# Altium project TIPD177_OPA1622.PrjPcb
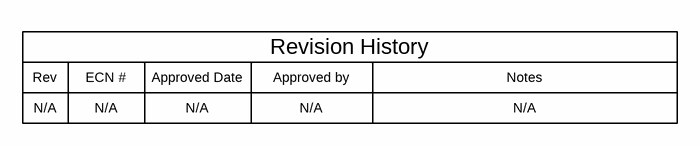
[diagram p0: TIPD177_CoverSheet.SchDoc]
TID: TIPD177; TechSupport: http://www.ti.com/support; SCH_Rev: E1; PRJ_Title: Headphone Amplifier; PRJ_Number: TIPD177; PRJ_Engineer: JC, CW; PRJ_Customer: Public Release; PCB_Rev: E1; PCB_Layout: CW; CopyrightYear: 2016
3 sheets, 71 parts. Net scope: global (net labels, ports and power ports of the same name join across sheets).
Board file: TIPD177.PcbDoc
Sheets:
  TIPD177_CoverSheet.SchDoc
  TIPD177_Main.SchDoc
  TIPD177_Hardware.SchDoc

## Sheet TIPD177_CoverSheet.SchDoc
size 431 x 279 mm; Date: Not shown in title block; ApprovedBy: Not shown in title block; CheckedBy: Not shown in title block; Author: Not shown in title block; CompanyName: Not shown in title block; Engineer: Not shown in title block; Organization: Not shown in title block; Address1: Not shown in title block; Address2: Not shown in title block; Address3: Not shown in title block; Address4: Not shown in title block; DocumentNumber: 1; Revision: Use project parameter SCH_Rev; SheetNumber: 1; SheetTotal: 3; PageSetup: Record=PageOptions¦CenterHorizontal=True¦CenterVertical=True¦PrintScale=1.00¦XCorrection=1.00¦YCorrection=1.00¦PrintKind=0¦BorderSize=5000000¦LeftOffset=0¦BottomOffset=0¦Orientation=2¦PaperLength=1000¦PaperWidth=1000¦Scale=100¦PaperSource=15¦PrintQuality=600¦MediaType=1¦DitherType=10¦PaperKind=Letter¦PrintScaleMode=1

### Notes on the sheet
- Rev
- N/A
- ECN #
- Approved Date
- Approved by
- Revision History
- Notes

## Sheet TIPD177_Main.SchDoc
size 431 x 279 mm; Date: Not shown in title block; ApprovedBy: Not shown in title block; CheckedBy: Not shown in title block; Author: Not shown in title block; CompanyName: Not shown in title block; Engineer: Not shown in title block; Organization: Not shown in title block; Address1: Not shown in title block; Address2: Not shown in title block; Address3: Not shown in title block; Address4: Not shown in title block; DocumentNumber: 1; Revision: Use project parameter SCH_Rev; SheetNumber: 2; SheetTotal: 3; PageSetup: Record=PageOptions¦CenterHorizontal=True¦CenterVertical=True¦PrintScale=0.62¦XCorrection=1.00¦YCorrection=1.00¦PrintKind=0¦BorderSize=5000000¦LeftOffset=0¦BottomOffset=0¦Orientation=2¦PaperLength=1000¦PaperWidth=1000¦Scale=100¦PaperSource=15¦PrintQuality=600¦MediaType=1¦DitherType=10¦PrintScaleMode=1¦PaperKind=Letter
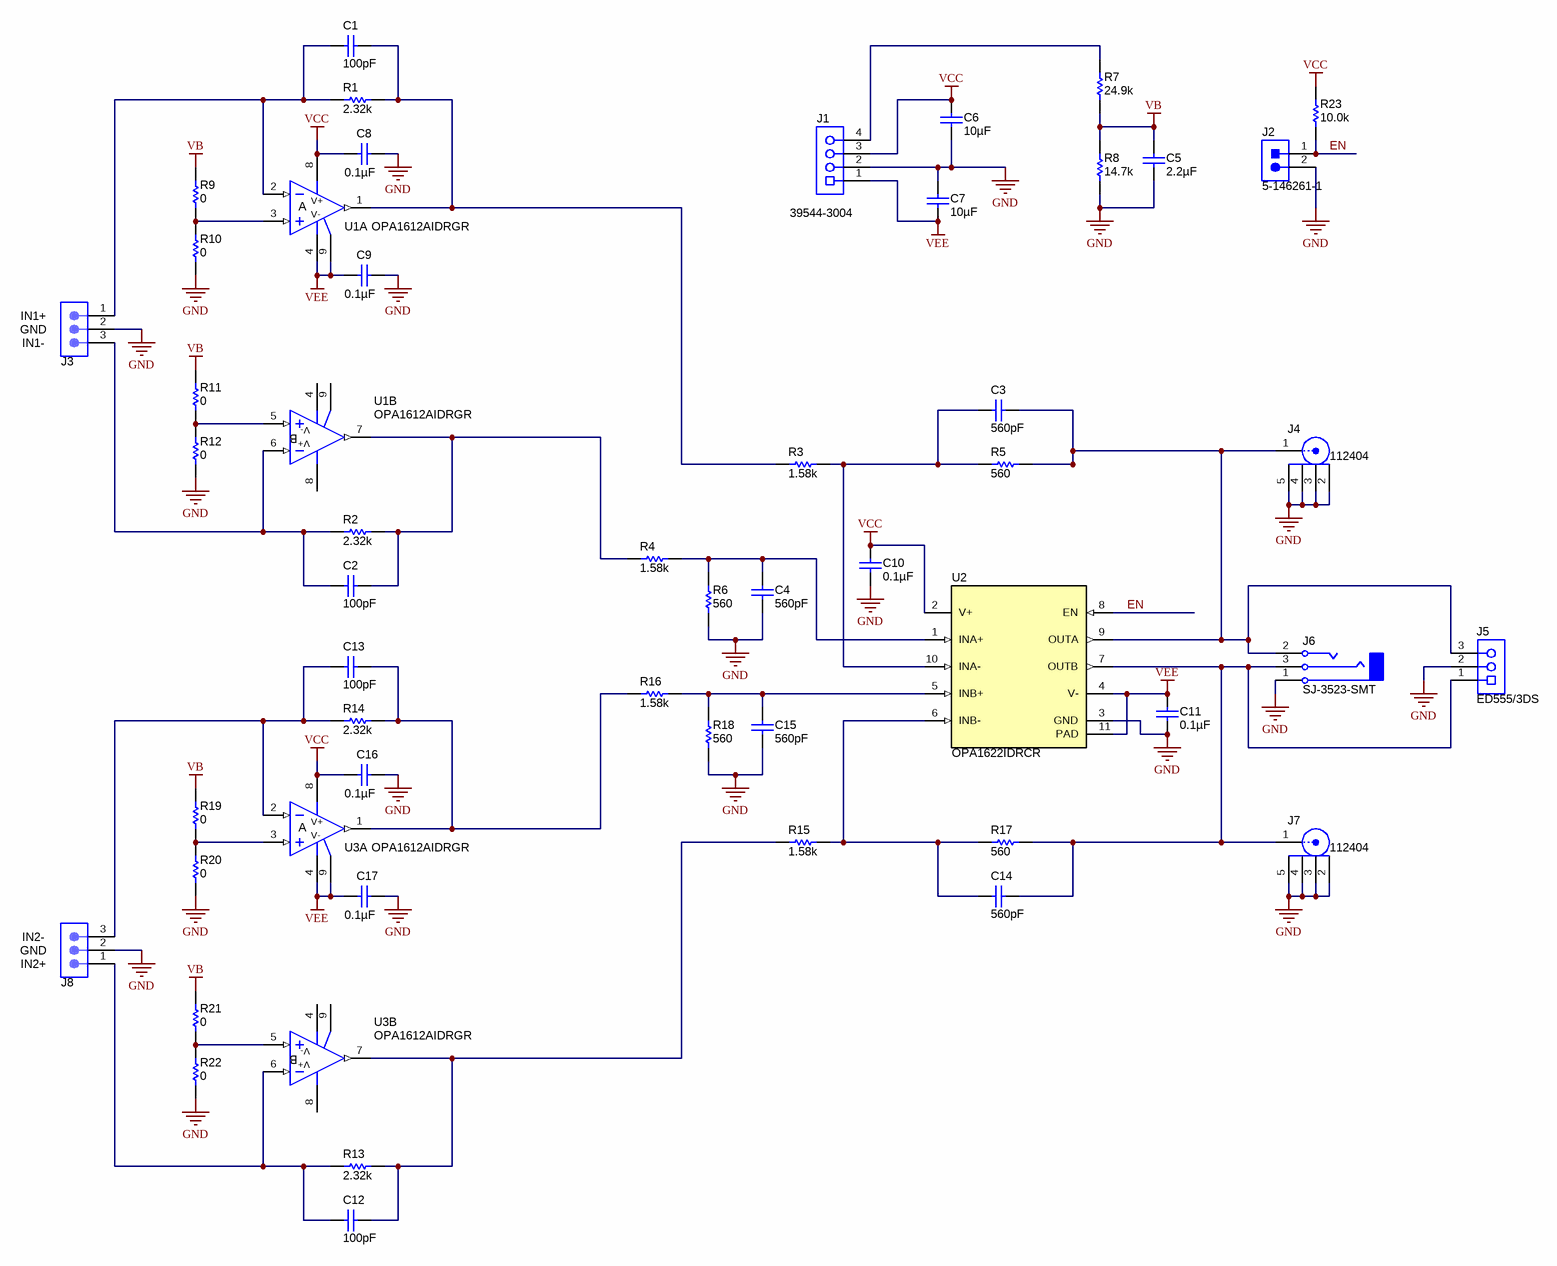
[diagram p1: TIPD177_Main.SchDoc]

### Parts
C1  ValueDisplayed: 100pF  [0603]  (hidden comment: GRM1885C1H101JA01D)
C2  ValueDisplayed: 100pF  [0603]  (hidden comment: GRM1885C1H101JA01D)
C3  ValueDisplayed: 560pF  [0603]  (hidden comment: GRM1885C1H561JA01D)
C4  ValueDisplayed: 560pF  [0603]  (hidden comment: GRM1885C1H561JA01D)
C5  ValueDisplayed: 2.2µF  [1206]  (hidden comment: GRM316R61E225KA12D)
C6  ValueDisplayed: 10µF  [1206]  (hidden comment: C3216X5R1C106M)
C7  ValueDisplayed: 10µF  [1206]  (hidden comment: C3216X5R1C106M)
C8  ValueDisplayed: 0.1µF  [0603]  (hidden comment: GRM188R71H104KA93D)
C9  ValueDisplayed: 0.1µF  [0603]  (hidden comment: GRM188R71H104KA93D)
C10  ValueDisplayed: 0.1µF  [0603]  (hidden comment: GRM188R71H104KA93D)
C11  ValueDisplayed: 0.1µF  [0603]  (hidden comment: GRM188R71H104KA93D)
C12  ValueDisplayed: 100pF  [0603]  (hidden comment: GRM1885C1H101JA01D)
C13  ValueDisplayed: 100pF  [0603]  (hidden comment: GRM1885C1H101JA01D)
C14  ValueDisplayed: 560pF  [0603]  (hidden comment: GRM1885C1H561JA01D)
C15  ValueDisplayed: 560pF  [0603]  (hidden comment: GRM1885C1H561JA01D)
C16  ValueDisplayed: 0.1µF  [0603]  (hidden comment: GRM188R71H104KA93D)
C17  ValueDisplayed: 0.1µF  [0603]  (hidden comment: GRM188R71H104KA93D)
J1  39544-3004  [MOLEX_39544-3004]
J2  5-146261-1  [CONN_5-146261-1]
J3  PBC03SAAN  [PBC03SAAN]  (value not drawn)
J4  112404  [Amphenol_112404]
J5  ED555/3DS  [TERM_BLK_ED555-3DS]
J6  SJ-3523-SMT  [CUI_SJ-3523-SMT]
J7  112404  [Amphenol_112404]
J8  PBC03SAAN  [PBC03SAAN]  (value not drawn)
R1  ValueDisplayed: 2.32k  [0603]  (hidden comment: RT0603BRD072K32L)
R2  ValueDisplayed: 2.32k  [0603]  (hidden comment: RT0603BRD072K32L)
R3  ValueDisplayed: 1.58k  [0603]  (hidden comment: RT0603BRD071K58L)
R4  ValueDisplayed: 1.58k  [0603]  (hidden comment: RT0603BRD071K58L)
R5  ValueDisplayed: 560  [0603]  (hidden comment: RG1608P-561-B-T5)
R6  ValueDisplayed: 560  [0603]  (hidden comment: RG1608P-561-B-T5)
R7  ValueDisplayed: 24.9k  [0603]  (hidden comment: RT0603BRD0724K9L)
R8  ValueDisplayed: 14.7k  [0603]  (hidden comment: RT0603BRD0714K7L)
R9  ValueDisplayed: 0  [0603]  (hidden comment: CRCW06030000Z0EA)
R10  ValueDisplayed: 0  [0603]  (hidden comment: CRCW06030000Z0EA)
R11  ValueDisplayed: 0  [0603]  (hidden comment: CRCW06030000Z0EA)
R12  ValueDisplayed: 0  [0603]  (hidden comment: CRCW06030000Z0EA)
R13  ValueDisplayed: 2.32k  [0603]  (hidden comment: RT0603BRD072K32L)
R14  ValueDisplayed: 2.32k  [0603]  (hidden comment: RT0603BRD072K32L)
R15  ValueDisplayed: 1.58k  [0603]  (hidden comment: RT0603BRD071K58L)
R16  ValueDisplayed: 1.58k  [0603]  (hidden comment: RT0603BRD071K58L)
R17  ValueDisplayed: 560  [0603]  (hidden comment: RG1608P-561-B-T5)
R18  ValueDisplayed: 560  [0603]  (hidden comment: RG1608P-561-B-T5)
R19  ValueDisplayed: 0  [0603]  (hidden comment: CRCW06030000Z0EA)
R20  ValueDisplayed: 0  [0603]  (hidden comment: CRCW06030000Z0EA)
R21  ValueDisplayed: 0  [0603]  (hidden comment: CRCW06030000Z0EA)
R22  ValueDisplayed: 0  [0603]  (hidden comment: CRCW06030000Z0EA)
R23  value 10.0k  [0603]  (hidden comment: CRCW060310K0FKEA)
U1  OPA1612AIDRGR  [DRG0008A]  (parts A,B of 2)
U2  OPA1622IDRCR  [DRC0010J]
U3  OPA1612AIDRGR  [DRG0008A]  (parts A,B of 2)

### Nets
GND: C4.1 C5.2 C6.2 C7.2 C8.1 C9.1 C10.2 C11.2 C15.1 C16.1 C17.1 J1.2 J2.2 J3.2 J4.2 J4.3 J4.4 J4.5 J5.2 J6.1(SLEEVE) J7.2 J7.3 J7.4 J7.5 J8.2 R6.2 R8.1 R10.1 R12.1 R18.2 R20.1 R22.1 U2.3(GND)
VB: C5.1 R7.1 R8.2 R9.2 R11.2 R19.2 R21.2
VCC: C6.1 C8.2 C10.1 C16.2 J1.3 R23.2 U1.8(V+) U2.2(V+) U3.8(V+)
VEE: C7.1 C9.2 C11.1 C17.2 J1.1 U1.4(V-) U1.9(PAD) U2.4(V-) U2.11(PAD) U3.4(V-) U3.9(PAD)
EN: J2.1 R23.1 U2.8(EN)
NetC1_1: C1.1 R1.2 R3.1 U1.1(OUT)
NetC1_2: C1.2 J3.1 R1.1 U1.2(IN-)
NetC2_1: C2.1 R2.2 R4.1 U1.7(OUT)
NetC2_2: C2.2 J3.3 R2.1 U1.6(IN-)
NetC3_1: C3.1 J4.1 J5.3 J6.2(TIP) R5.2 U2.9(OUTA)
NetC3_2: C3.2 R3.2 R5.1 U2.10(INA-)
NetC4_2: C4.2 R4.2 R6.1 U2.1(INA+)
NetC12_1: C12.1 R13.2 R15.1 U3.7(OUT)
NetC12_2: C12.2 J8.1 R13.1 U3.6(IN-)
NetC13_1: C13.1 R14.2 R16.1 U3.1(OUT)
NetC13_2: C13.2 J8.3 R14.1 U3.2(IN-)
NetC14_1: C14.1 J5.1 J6.3(RING) J7.1 R17.2 U2.7(OUTB)
NetC14_2: C14.2 R15.2 R17.1 U2.6(INB-)
NetC15_2: C15.2 R16.2 R18.1 U2.5(INB+)
NetJ1_4: J1.4 R7.2
NetR9_1: R9.1 R10.2 U1.3(IN+)
NetR11_1: R11.1 R12.2 U1.5(IN+)
NetR19_1: R19.1 R20.2 U3.3(IN+)
NetR21_1: R21.1 R22.2 U3.5(IN+)

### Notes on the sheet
- (near J3) IN1-
- (near J3) IN1+
- (near J3) GND
- (near J8) IN2-
- (near J8) GND
- (near J8) IN2+

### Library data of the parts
C1 C2 C12 C13 = GRM1885C1H101JA01D: CAP, CERM, 100 pF, 50 V, +/- 5%, C0G/NP0, 0603; Manufacturer: MuRata; Polarized: N; CompType: Capacitor; Value: 100pF; U/M: EA; Cap_F: 0.0000000001; Tolerance_%: 5; Value1: Unknown; VDC_V: 50; Value2: 50V; TaMin_C: -55; TaMax_C: 125; AEC Category: Q200
C3 C4 C14 C15 = GRM1885C1H561JA01D: CAP, CERM, 560 pF, 50 V, +/- 5%, C0G/NP0, 0603; Manufacturer: MuRata; Polarized: N; CompType: Capacitor; Value: 560pF; U/M: EA; Cap_F: 0.00000000056; Tolerance_%: 5; Value1: Unknown; VDC_V: 50; Value2: 50V; TaMin_C: -55; TaMax_C: 125; AEC Category: Q200
C5 = GRM316R61E225KA12D: CAP, CERM, 2.2uF, 25V, +/-10%, X5R, 1206; Manufacturer: MuRata; Polarized: N; CompType: Capacitor; U/M: EA; Cap_F: 0.0000022; Tolerance_%: 10; ESR_Ohm: 0.006; Value1: 0.006 ohm; VDC_V: 25; TaMin_C: -55; TaMax_C: 85
C6 C7 = C3216X5R1C106M: CAP, CERM, 10uF, 16V, +/-20%, X5R, 1206; Manufacturer: TDK; Polarized: N; CompType: Capacitor; U/M: EA; Cap_F: 0.00001; Tolerance_%: 20; ESR_Ohm: 0.0046; Value1: 0.0046 ohm; VDC_V: 16; IRMS_A: 2.7; TaMin_C: -55; TaMax_C: 85
C8-C11 C16 C17 = GRM188R71H104KA93D: CAP, CERM, 0.1 µF, 50 V, +/- 10%, X7R, 0603; Manufacturer: MuRata; Polarized: N; CompType: Capacitor; Value: 0.1uF; U/M: EA; Cap_F: 0.0000001; Tolerance_%: 10; Value1: Unknown; VDC_V: 50; Value2: 50V; TaMin_C: -55; TaMax_C: 125; AEC Category: Q200
J1 = 39544-3004: Terminal Block, 4x1, 5.08mm, TH; Manufacturer: Molex; SymbolCreator: a0411947
J2 = 5-146261-1: Header, 100mil, 2x1, Gold, TH; Manufacturer: TE Connectivity; SymbolCreator: a0412235
J3 J8 = PBC03SAAN: Header, 100mil, 3x1, Gold, TH; Manufacturer: Sullins Connector Solutions
J4 J7 = 112404: Connector, TH, BNC; Manufacturer: Amphenol Connex
J5 = ED555/3DS: Terminal Block, 3.5mm Pitch, 3x1, TH; Manufacturer: On-Shore Technology; SymbolCreator: a0412235; Pitch_mm: 3.5; Gender: Female; Shrouded: N; Row_Count: 1; ContactFinish: Brass; Current_A: 6; Voltage_V: 150; Cert_CULUS: Y
J6 = SJ-3523-SMT: Audio Jack, 3.5mm, Stereo, R/A, SMT; Manufacturer: CUI Inc.; SymbolCreator: a0412235
R1 R2 R13 R14 = RT0603BRD072K32L: RES, 2.32 k, 0.1%, 0.1 W, 0603; Manufacturer: Yageo America; CompType: Resistor; Value: 2.32k; Res_ohm: 2320; Value_Code: 2k32; Tolerance_%: 0.1; Value2: 0.1W; VDC_V: 75; TempCo: 25 ppm/C; EIA_Code: E192; U/M: EA; AEC Category: Q200
R3 R4 R15 R16 = RT0603BRD071K58L: RES, 1.58 k, 0.1%, 0.1 W, 0603; Manufacturer: Yageo America; CompType: Resistor; Value: 1.58k; Res_ohm: 1580; Value_Code: 1k58; Tolerance_%: 0.1; Value2: 0.1W; VDC_V: 75; TempCo: 25 ppm/C; EIA_Code: E192; U/M: EA; AEC Category: Q200
R5 R6 R17 R18 = RG1608P-561-B-T5: RES, 560, 0.1%, 0.1 W, 0603; Manufacturer: Susumu Co Ltd; CompType: Resistor; Value: 560; Value_Code: 560R; Tolerance_%: 0.1; Value2: 0.1W; VDC_V: 75; TempCo: 25 ppm/C; U/M: EA; AEC Category: Q200
R7 = RT0603BRD0724K9L: RES, 24.9 k, 0.1%, 0.1 W, 0603; Manufacturer: Yageo America; CompType: Resistor; Value: 24.9k; Res_ohm: 24900; Value_Code: 24k9; Tolerance_%: 0.1; Value2: 0.1W; VDC_V: 75; TempCo: 25 ppm/C; EIA_Code: E192; U/M: EA; AEC Category: Q200
R8 = RT0603BRD0714K7L: RES, 14.7 k, 0.1%, 0.1 W, 0603; Manufacturer: Yageo America; CompType: Resistor; Value: 14.7k; Res_ohm: 14700; Value_Code: 14k7; Tolerance_%: 0.1; Value2: 0.1W; VDC_V: 75; TempCo: 25 ppm/C; EIA_Code: E192; U/M: EA; AEC Category: Q200
R9-R12 R19-R22 = CRCW06030000Z0EA: RES, 0, 5%, 0.1 W, 0603; Manufacturer: Vishay-Dale; CompType: Resistor; Value: 0; Value_Code: 0000; Tolerance_%: 5; Power_W: 0.1; Value2: 0.1W; VDC_V: 75; TempCo: 200 ppm/C; EIA_Code: E24; U/M: EA; AEC Category: Q200
R23 = CRCW060310K0FKEA: RES, 10.0k ohm, 1%, 0.1W, 0603; Manufacturer: Vishay-Dale; CompType: Resistor; Res_ohm: 10000; Value_Code: 10k0; Tolerance_%: 1; Power_W: 0.1; VDC_V: 75; TempCo: 100 ppm/C; EIA_Code: E96; U/M: EA
U1 U3 = OPA1612AIDRGR: SoundPlus High-Performance, Bipolar-Input Audio Operational Amplifiers, DRG0008A; Alternate PartNumber: OPA1612AIDRGT; Manufacturer: Texas Instruments; SymbolCreator: a0411947; CompType: IC; U/M: EA
U2 = OPA1622IDRCR: SoundPlus High-Fidelity, Bipolar-Input, Audio Operational Amplifier, DRC0010J; Alternate PartNumber: OPA1622IDRCT; Manufacturer: Texas Instruments; SymbolCreator: Altium; CompType: IC; U/M: EA

## Sheet TIPD177_Hardware.SchDoc
size 431 x 279 mm; Date: Not shown in title block; ApprovedBy: Not shown in title block; CheckedBy: Not shown in title block; Author: Not shown in title block; CompanyName: Not shown in title block; Engineer: Not shown in title block; Organization: Not shown in title block; Address1: Not shown in title block; Address2: Not shown in title block; Address3: Not shown in title block; Address4: Not shown in title block; DocumentNumber: 1; Revision: Use project parameter SCH_Rev; SheetNumber: 3; SheetTotal: 3; PageSetup: Record=PageOptions¦CenterHorizontal=True¦CenterVertical=True¦PrintScale=1.00¦XCorrection=1.00¦YCorrection=1.00¦PrintKind=0¦BorderSize=5000000¦LeftOffset=0¦BottomOffset=0¦Orientation=2¦PaperLength=1000¦PaperWidth=1000¦Scale=100¦PaperSource=15¦PrintQuality=600¦MediaType=1¦DitherType=10¦PaperKind=Letter¦PrintScaleMode=1
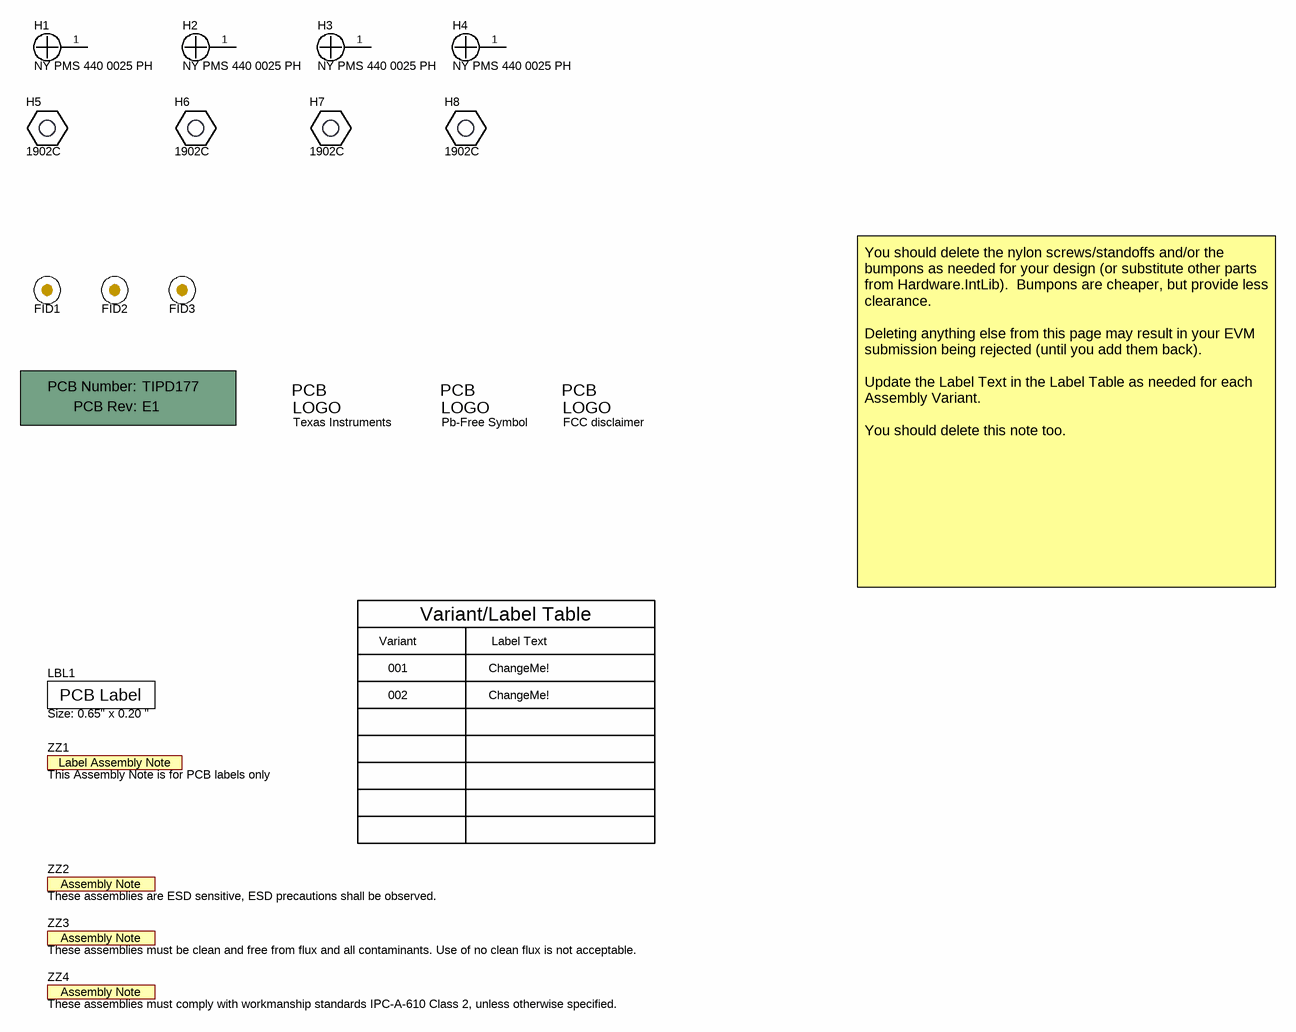
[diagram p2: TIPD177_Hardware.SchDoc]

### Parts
!PCB1  Printed Circuit Board  (value not drawn)  (mechanical)
FID1  Fiducial  [Fiducial10-20]  (value not drawn)
FID2  Fiducial  [Fiducial10-20]  (value not drawn)
FID3  Fiducial  [Fiducial10-20]  (value not drawn)
H1  NY PMS 440 0025 PH  [NY PMS 440 0025 PH]
H2  NY PMS 440 0025 PH  [NY PMS 440 0025 PH]
H3  NY PMS 440 0025 PH  [NY PMS 440 0025 PH]
H4  NY PMS 440 0025 PH  [NY PMS 440 0025 PH]
H5  1902C  [Keystone_1902C]
H6  1902C  [Keystone_1902C]
H7  1902C  [Keystone_1902C]
H8  1902C  [Keystone_1902C]
LBL1  Size: 0.65" x 0.20 "  [Label_650x200]
Logo1  Texas Instruments  [TI_Stacked_Overlay_Small]  (no BOM)
Logo2  Pb-Free Symbol  [Pb-Free_Overlay_Small]  (no BOM)
Logo3  FCC disclaimer  [FCC_disclaimer]  (no BOM)
ZZ1  This Assembly Note is for PCB labels only  [AssemblyNoteLabel]  (no BOM)
ZZ2  These assemblies are ESD sensitive, ESD precautions shall be observed.  [AssemblyNote]  (no BOM)
ZZ3  These assemblies must be clean and free from flux and all contaminants. Use of no clean flux is not acceptable.  [AssemblyNote]  (no BOM)
ZZ4  These assemblies must comply with workmanship standards IPC-A-610 Class 2, unless otherwise specified.  [AssemblyNote]  (no BOM)

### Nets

Not connected (* = marked no-connect by the designer): H1 1; H2 1; H3 1; H4 1

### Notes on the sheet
- Variant
- Variant/Label Table
- Label Text
- You should delete the nylon screws/standoffs and/or the bumpons as needed for your design (or substitute other parts from Hardware.IntLib).  Bumpons are cheaper, but provide less clearance.
  Deleting anything else from this page may result in your EVM submission being rejected (until you add them back).
  Update the Label Text in the Label Table as needed for each Assembly Variant.
  You should delete this note too.
- 001
- 002
- ChangeMe!

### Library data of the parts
!PCB1 = PCB: Manufacturer: Any; PartNumber: TIPD177; SymbolCreator: a0412235
FID1-FID3 = Fiducial: Fiducial mark.  There is nothing to buy or mount.; SymbolCreator: codlsc
H1-H4 = NY PMS 440 0025 PH: Machine Screw, Round, #4-40 x 1/4, Nylon, Philips panhead; Manufacturer: B&F Fastener Supply; CompType: Hardware; SymbolCreator: codlsc; U/M: EA
H5-H8 = 1902C: Standoff, Hex, 0.5"L #4-40 Nylon; Manufacturer: Keystone; CompType: Hardware
LBL1 = THT-14-423-10: Thermal Transfer Printable Labels, 0.650" W x 0.200" H - 10,000 per roll; Manufacturer: Brady; SymbolCreator: a0412235; CompType: Label
Logo1 = TI_Logo: Texas Instrument Corporate Signature; SymbolCreator: codlsc
Logo2 = Pb-Free: SymbolCreator: a0412235
Logo3 = FCC_disclaimer: SymbolCreator: codlsc
ZZ1 = AssemblyNoteLabel: SymbolCreator: a0412235
ZZ2-ZZ4 = AssemblyNote: SymbolCreator: codlsc

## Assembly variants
001: not fitted FID1 FID2 FID3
